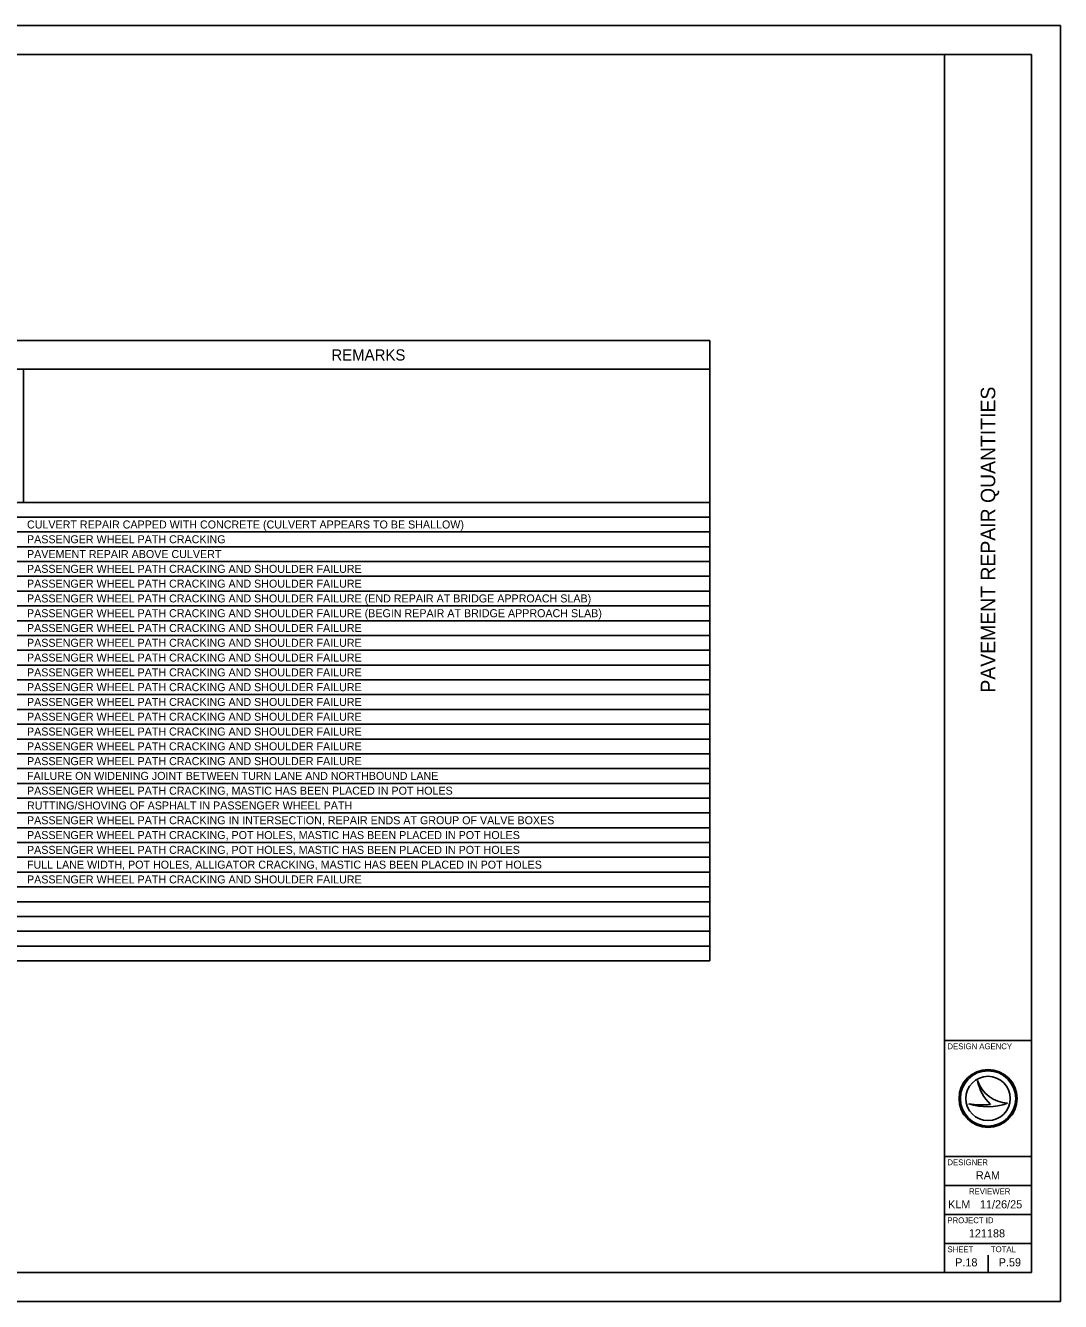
# Model space of a CAD drawing. Extents: x 0 to 34, y 0 to 22.
# Drawn here: x 16.15 to 34, y 0 to 22 of the extents above; entities that cross this region are included whole.
import ezdxf

# ---------------------------------------------------------------- set-up
doc = ezdxf.new("R2010")
doc.units = 0
for name, color, linetype in [('SH_Border', 7, 'Continuous'), ('SH_Cut_Line', 7, 'Continuous'), ('SH_Data', 7, 'Continuous'), ('SH_Text', 7, 'Continuous')]:
    doc.layers.add(name, color=color, linetype=linetype)

msp = doc.modelspace()

# ---------------------------------------------------------------- linework, layer by layer
at = {"layer": 'SH_Border'}
for p, q in [((32, 0.5), (32, 21.5)), ((32, 4.5), (33.5, 4.5)), ((32, 2.5), (33.5, 2.5)), ((32, 2), (33.5, 2)), ((32, 1.5), (33.5, 1.5)), ((32, 1), (33.5, 1))]:
    msp.add_line(p, q, dxfattribs=at)
msp.add_lwpolyline([(1.5, 21.5), (33.5, 21.5), (33.5, 0.5), (1.5, 0.5)], close=True, dxfattribs=at)
at = {"layer": 'SH_Cut_Line'}
msp.add_lwpolyline([(0, 0), (34, 0), (34, 22), (0, 22)], close=True, dxfattribs=at)
at = {"layer": 'SH_Data'}
for p, q in [((32.567, 3.81), (32.567, 3.81)), ((32.417, 3.41), (32.417, 3.41)), ((32.75, 3.5), (32.75, 3.5)), ((33.087, 3.419), (33.087, 3.419)), ((32.375, 0.675), (32.375, 0.675)), ((32.75, 0.5), (32.75, 0.8))]:
    msp.add_line(p, q, dxfattribs=at)
for radius in [0.5, 0.477, 0.477, 0.382]:
    msp.add_circle((32.75, 3.5), radius, dxfattribs=at)
for centre, radius, start, end in [((33.116, 3.998), 0.58, 198.9257, 198.9319), ((33.347, 3.97), 0.796, 191.6379, 191.6421), ((33.116, 3.998), 0.58, 198.9319, 267.1657), ((33.347, 3.97), 0.796, 191.6421, 226.0947), ((32.739, 4.37), 1.013, 251.4576, 290.0832), ((32.648, 4.654), 1.266, 259.4964, 259.4995), ((32.739, 4.37), 1.013, 251.4527, 251.4576), ((32.648, 4.654), 1.266, 259.4995, 276.6672)]:
    msp.add_arc(centre, radius, start, end, dxfattribs=at)
at = {"layer": 'SH_Text'}
for p, q in [((5.255, 16.568), (27.95, 16.568)), ((27.95, 16.568), (27.95, 5.873)), ((5.255, 16.073), (27.95, 16.073)), ((5.255, 13.778), (27.95, 13.778)), ((5.255, 13.523), (27.95, 13.523)), ((5.255, 13.268), (27.95, 13.268)), ((5.255, 13.013), (27.95, 13.013)), ((5.255, 12.758), (27.95, 12.758)), ((5.255, 12.503), (27.95, 12.503)), ((5.255, 12.248), (27.95, 12.248)), ((5.255, 11.993), (27.95, 11.993)), ((5.255, 11.738), (27.95, 11.738)), ((5.255, 11.483), (27.95, 11.483)), ((5.255, 11.228), (27.95, 11.228)), ((5.255, 10.973), (27.95, 10.973)), ((5.255, 10.718), (27.95, 10.718)), ((5.255, 10.463), (27.95, 10.463)), ((5.255, 10.208), (27.95, 10.208)), ((5.255, 9.953), (27.95, 9.953)), ((5.255, 9.698), (27.95, 9.698)), ((5.255, 9.443), (27.95, 9.443)), ((5.255, 9.188), (27.95, 9.188)), ((5.255, 8.933), (27.95, 8.933)), ((5.255, 8.678), (27.95, 8.678)), ((5.255, 8.423), (27.95, 8.423)), ((5.255, 8.168), (27.95, 8.168)), ((5.255, 7.913), (27.95, 7.913)), ((5.255, 7.658), (27.95, 7.658)), ((5.255, 7.403), (27.95, 7.403)), ((5.255, 7.148), (27.95, 7.148)), ((5.255, 6.893), (27.95, 6.893)), ((5.255, 6.638), (27.95, 6.638)), ((5.255, 6.383), (27.95, 6.383)), ((5.255, 6.128), (27.95, 6.128)), ((5.255, 5.873), (27.95, 5.873))]:
    msp.add_line(p, q, dxfattribs=at)
msp.add_lwpolyline([(16.115, 16.073), (27.95, 16.073), (27.95, 13.778), (16.115, 13.778)], close=True, dxfattribs=at)

# ---------------------------------------------------------------- texts
at = {"layer": 'SH_Data'}
msp.add_text('PAVEMENT REPAIR QUANTITIES', height=0.25, rotation=90, dxfattribs=at).set_placement((32.875, 10.498))
for s, height, p in [('DESIGN AGENCY', 0.1, (32.05, 4.35)), ('DESIGNER', 0.1, (32.05, 2.35)), ('RAM', 0.14, (32.541, 2.105)), ('REVIEWER', 0.1, (32.422, 1.85)), ('KLM', 0.14, (32.061, 1.605)), ('11/26/25', 0.14, (32.611, 1.605)), ('PROJECT ID', 0.1, (32.05, 1.35)), ('121188', 0.14, (32.419, 1.105)), ('SHEET', 0.1, (32.05, 0.85)), ('TOTAL', 0.1, (32.8, 0.85)), ('P.18', 0.14, (32.183, 0.605)), ('P.59', 0.14, (32.934, 0.605))]:
    msp.add_text(s, height=height, dxfattribs=at).set_placement(p)
at = {"layer": 'SH_Text'}
for s, height, p in [('REMARKS', 0.1932, (21.424, 16.224)), ('CULVERT REPAIR CAPPED WITH CONCRETE (CULVERT APPEARS TO BE SHALLOW)', 0.138, (16.175, 13.328)), ('PASSENGER WHEEL PATH CRACKING', 0.138, (16.175, 13.073)), ('PAVEMENT REPAIR ABOVE CULVERT', 0.138, (16.175, 12.818)), ('PASSENGER WHEEL PATH CRACKING AND SHOULDER FAILURE', 0.138, (16.175, 12.563)), ('PASSENGER WHEEL PATH CRACKING AND SHOULDER FAILURE', 0.138, (16.175, 12.308)), ('PASSENGER WHEEL PATH CRACKING AND SHOULDER FAILURE (END REPAIR AT BRIDGE APPROACH SLAB)', 0.138, (16.175, 12.053)), ('PASSENGER WHEEL PATH CRACKING AND SHOULDER FAILURE (BEGIN REPAIR AT BRIDGE APPROACH SLAB)', 0.138, (16.175, 11.798)), ('PASSENGER WHEEL PATH CRACKING AND SHOULDER FAILURE', 0.138, (16.175, 11.543)), ('PASSENGER WHEEL PATH CRACKING AND SHOULDER FAILURE', 0.138, (16.175, 11.288)), ('PASSENGER WHEEL PATH CRACKING AND SHOULDER FAILURE', 0.138, (16.175, 11.033)), ('PASSENGER WHEEL PATH CRACKING AND SHOULDER FAILURE', 0.138, (16.175, 10.778)), ('PASSENGER WHEEL PATH CRACKING AND SHOULDER FAILURE', 0.138, (16.175, 10.523)), ('PASSENGER WHEEL PATH CRACKING AND SHOULDER FAILURE', 0.138, (16.175, 10.268)), ('PASSENGER WHEEL PATH CRACKING AND SHOULDER FAILURE', 0.138, (16.175, 10.013)), ('PASSENGER WHEEL PATH CRACKING AND SHOULDER FAILURE', 0.138, (16.175, 9.758)), ('PASSENGER WHEEL PATH CRACKING AND SHOULDER FAILURE', 0.138, (16.175, 9.503)), ('PASSENGER WHEEL PATH CRACKING AND SHOULDER FAILURE', 0.138, (16.175, 9.248)), ('FAILURE ON WIDENING JOINT BETWEEN TURN LANE AND NORTHBOUND LANE', 0.138, (16.175, 8.993)), ('PASSENGER WHEEL PATH CRACKING, MASTIC HAS BEEN PLACED IN POT HOLES', 0.138, (16.175, 8.738)), ('RUTTING/SHOVING OF ASPHALT IN PASSENGER WHEEL PATH', 0.138, (16.175, 8.483)), ('PASSENGER WHEEL PATH CRACKING IN INTERSECTION, REPAIR ENDS AT GROUP OF VALVE BOXES', 0.138, (16.175, 8.228)), ('PASSENGER WHEEL PATH CRACKING, POT HOLES, MASTIC HAS BEEN PLACED IN POT HOLES', 0.138, (16.175, 7.973)), ('PASSENGER WHEEL PATH CRACKING, POT HOLES, MASTIC HAS BEEN PLACED IN POT HOLES', 0.138, (16.175, 7.718)), ('FULL LANE WIDTH, POT HOLES, ALLIGATOR CRACKING, MASTIC HAS BEEN PLACED IN POT HOLES', 0.138, (16.175, 7.463)), ('PASSENGER WHEEL PATH CRACKING AND SHOULDER FAILURE', 0.138, (16.175, 7.208))]:
    msp.add_text(s, height=height, dxfattribs=at).set_placement(p)

doc.saveas('drawing.dxf')
